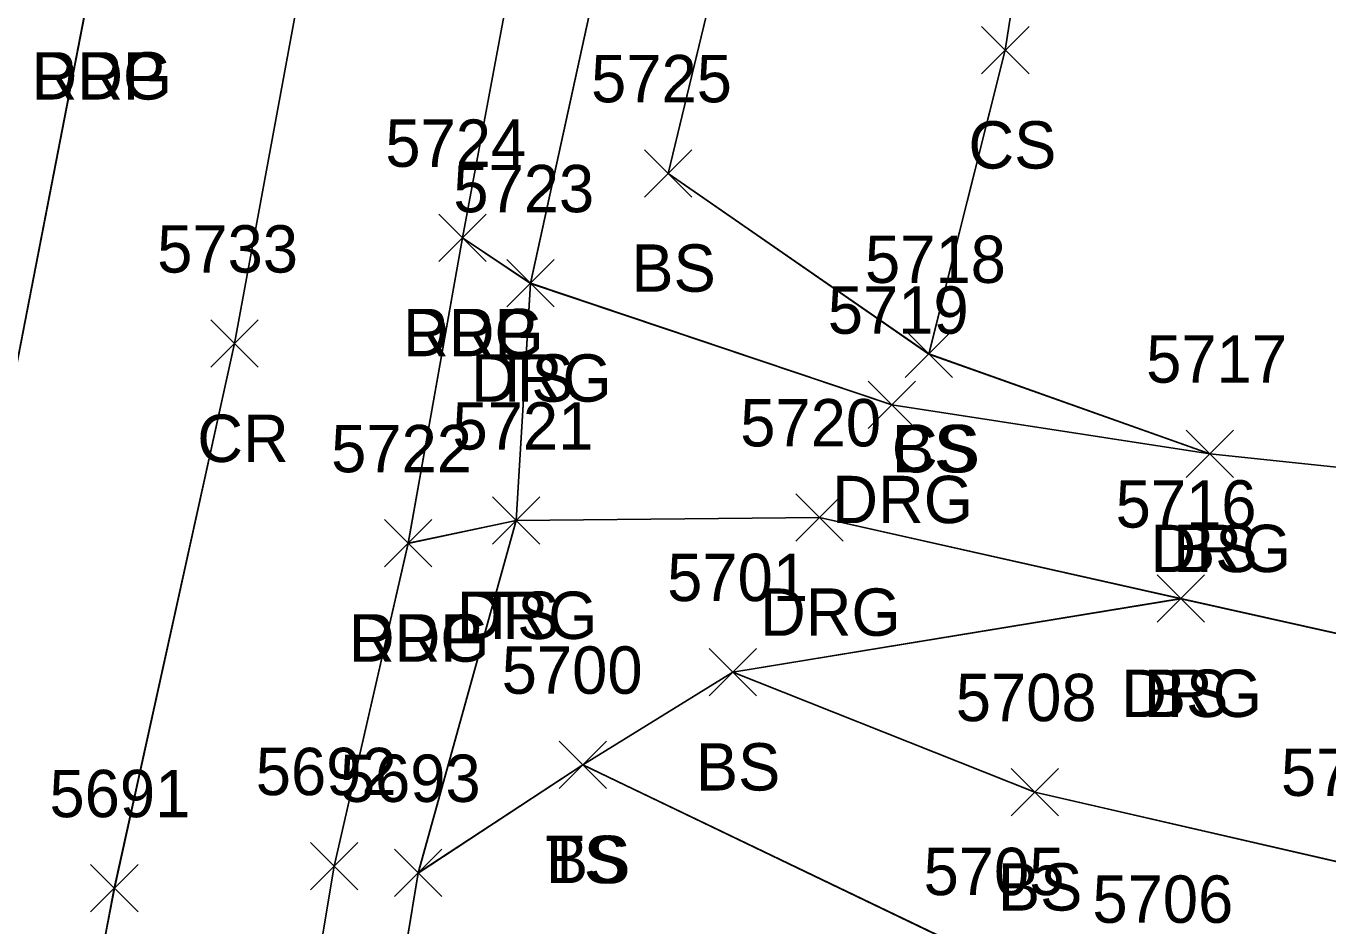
# Model space of a CAD drawing. Extents: x 1554668 to 1563881, y 831386 to 834374.
# Drawn here: x 1561791.4 to 1561846.4, y 833346.9 to 833385 of the extents above; entities that cross this region are included whole.
import ezdxf

# ---------------------------------------------------------------- set-up
doc = ezdxf.new("R2010")
doc.units = 0
for name, color, linetype in [('L_A', 7, 'Continuous'), ('L_I', 7, 'Continuous'), ('L_TIC', 7, 'Continuous'), ('LELB', 7, 'Continuous'), ('P_A', 7, 'Continuous'), ('P_I', 7, 'Continuous'), ('P_TIC', 7, 'Continuous'), ('PET', 7, 'Continuous'), ('PRC', 7, 'Continuous'), ('R_A', 7, 'Continuous'), ('R_I', 7, 'Continuous'), ('R_TIC', 7, 'Continuous'), ('RDG', 7, 'Continuous')]:
    doc.layers.add(name, color=color, linetype=linetype)

msp = doc.modelspace()

# ---------------------------------------------------------------- linework, layer by layer
at = {"layer": 'L_TIC'}
for points in [[(1561831.772, 833382.931), (1561833.772, 833384.931)], [(1561833.772, 833382.931), (1561831.772, 833384.931)], [(1561817.534, 833377.73), (1561819.534, 833379.73)], [(1561819.534, 833377.73), (1561817.534, 833379.73)], [(1561811.717, 833373.086), (1561813.717, 833375.086)], [(1561813.717, 833373.086), (1561811.717, 833375.086)], [(1561828.538, 833370.101), (1561830.538, 833372.101)], [(1561830.538, 833370.101), (1561828.538, 833372.101)], [(1561828.538, 833370.101), (1561830.538, 833372.101)], [(1561830.538, 833370.101), (1561828.538, 833372.101)], [(1561840.414, 833365.888), (1561842.414, 833367.888)], [(1561842.414, 833365.888), (1561840.414, 833367.888)], [(1561811.115, 833363.064), (1561813.115, 833365.064)], [(1561813.115, 833363.064), (1561811.115, 833365.064)], [(1561839.178, 833359.768), (1561841.178, 833361.768)], [(1561841.178, 833359.768), (1561839.178, 833361.768)], [(1561820.259, 833356.663), (1561822.259, 833358.663)], [(1561822.259, 833356.663), (1561820.259, 833358.663)], [(1561820.259, 833356.663), (1561822.259, 833358.663)], [(1561822.259, 833356.663), (1561820.259, 833358.663)], [(1561813.926, 833352.75), (1561815.926, 833354.75)], [(1561815.926, 833352.75), (1561813.926, 833354.75)], [(1561813.926, 833352.75), (1561815.926, 833354.75)], [(1561815.926, 833352.75), (1561813.926, 833354.75)], [(1561833.017, 833351.592), (1561835.017, 833353.592)], [(1561835.017, 833351.592), (1561833.017, 833353.592)], [(1561806.971, 833348.18), (1561808.971, 833350.18)], [(1561808.971, 833348.18), (1561806.971, 833350.18)], [(1561806.971, 833348.18), (1561808.971, 833350.18)], [(1561808.971, 833348.18), (1561806.971, 833350.18)]]:
    msp.add_lwpolyline(points, dxfattribs=at)
at = {"layer": 'LELB'}
for points in [[(1561841.414, 833366.888), (1561829.538, 833371.101), (1561818.534, 833378.73), (1561823.688, 833400.076), (1561828.271, 833434.265), (1561833.191, 833445.334), (1561836.067, 833469.47), (1561840.466, 833492.775), (1561845.508, 833506.736), (1561853.324, 833557.227)], [(1561841.414, 833366.885), (1561829.538, 833371.095), (1561818.535, 833378.726), (1561823.688, 833400.072), (1561828.271, 833434.262), (1561833.192, 833445.33), (1561836.066, 833469.461), (1561840.465, 833492.765), (1561845.509, 833506.732), (1561853.326, 833557.225)], [(1561841.414, 833366.885), (1561829.538, 833371.095), (1561818.535, 833378.726), (1561823.688, 833400.072), (1561828.271, 833434.262), (1561833.192, 833445.33), (1561836.066, 833469.461), (1561840.465, 833492.765), (1561845.509, 833506.732), (1561853.326, 833557.225)], [(1561841.414, 833366.885), (1561829.538, 833371.095), (1561818.535, 833378.726), (1561823.688, 833400.072), (1561828.271, 833434.262), (1561833.192, 833445.33), (1561836.066, 833469.461), (1561840.465, 833492.765), (1561845.509, 833506.732), (1561853.326, 833557.225)], [(1561829.538, 833371.101), (1561832.772, 833383.931), (1561835.237, 833399.815), (1561850.214, 833430.878)], [(1561829.538, 833371.095), (1561832.772, 833383.929), (1561835.236, 833399.812), (1561850.216, 833430.872)], [(1561829.538, 833371.095), (1561832.772, 833383.929), (1561835.236, 833399.812), (1561850.216, 833430.872)], [(1561829.538, 833371.095), (1561832.772, 833383.929), (1561835.236, 833399.812), (1561850.216, 833430.872)], [(1561802.802, 833317.896), (1561807.971, 833349.18), (1561812.115, 833364.064), (1561812.717, 833374.086), (1561818.657, 833401.257)], [(1561802.805, 833317.894), (1561807.975, 833349.179), (1561812.115, 833364.063), (1561812.716, 833374.079), (1561818.656, 833401.248)], [(1561802.805, 833317.894), (1561807.975, 833349.179), (1561812.115, 833364.063), (1561812.716, 833374.079), (1561818.656, 833401.248)], [(1561802.805, 833317.894), (1561807.975, 833349.179), (1561812.115, 833364.063), (1561812.716, 833374.079), (1561818.656, 833401.248)], [(1561807.971, 833349.18), (1561814.926, 833353.75), (1561821.259, 833357.663), (1561840.178, 833360.768)], [(1561807.975, 833349.179), (1561814.926, 833353.748), (1561821.259, 833357.662), (1561840.179, 833360.759)], [(1561807.975, 833349.179), (1561814.926, 833353.748), (1561821.259, 833357.662), (1561840.179, 833360.759)], [(1561807.975, 833349.179), (1561814.926, 833353.748), (1561821.259, 833357.662), (1561840.179, 833360.759)], [(1561821.259, 833357.663), (1561834.017, 833352.592), (1561847.759, 833349.436), (1561844.879, 833338.765)], [(1561821.259, 833357.662), (1561834.017, 833352.592), (1561847.76, 833349.427), (1561844.878, 833338.763)], [(1561821.259, 833357.662), (1561834.017, 833352.592), (1561847.76, 833349.427), (1561844.878, 833338.763)], [(1561821.259, 833357.662), (1561834.017, 833352.592), (1561847.76, 833349.427), (1561844.878, 833338.763)], [(1561814.926, 833353.75), (1561832.657, 833345.244), (1561839.843, 833344.075), (1561839.671, 833339.692)], [(1561814.926, 833353.748), (1561832.658, 833345.234), (1561839.843, 833344.071), (1561839.671, 833339.686)], [(1561814.926, 833353.748), (1561832.658, 833345.234), (1561839.843, 833344.071), (1561839.671, 833339.686)], [(1561814.926, 833353.748), (1561832.658, 833345.234), (1561839.843, 833344.071), (1561839.671, 833339.686)]]:
    msp.add_lwpolyline(points, dxfattribs=at)
at = {"layer": 'P_TIC'}
for points in [[(1561808.846, 833375.005), (1561810.846, 833377.005)], [(1561810.846, 833375.005), (1561808.846, 833377.005)], [(1561799.21, 833370.538), (1561801.21, 833372.538)], [(1561801.21, 833370.538), (1561799.21, 833372.538)], [(1561806.557, 833362.104), (1561808.557, 833364.104)], [(1561808.557, 833362.104), (1561806.557, 833364.104)], [(1561803.42, 833348.467), (1561805.42, 833350.467)], [(1561805.42, 833348.467), (1561803.42, 833350.467)], [(1561794.14, 833347.536), (1561796.14, 833349.536)], [(1561796.14, 833347.536), (1561794.14, 833349.536)]]:
    msp.add_lwpolyline(points, dxfattribs=at)
at = {"layer": 'PET'}
for points in [[(1561772.446, 833192.579), (1561778.438, 833223.18), (1561783.455, 833245.681), (1561787.292, 833266.873), (1561787.951, 833268.214), (1561791.576, 833284.83), (1561800.188, 833324.049), (1561804.421, 833349.461), (1561807.556, 833363.095), (1561809.846, 833376.001), (1561814.768, 833402.403)], [(1561772.446, 833192.579), (1561778.438, 833223.18), (1561783.455, 833245.681), (1561787.292, 833266.873), (1561787.951, 833268.214), (1561791.576, 833284.83), (1561800.188, 833324.049), (1561804.421, 833349.461), (1561807.556, 833363.095), (1561809.846, 833376.001), (1561814.768, 833402.403)], [(1561772.446, 833192.579), (1561778.438, 833223.18), (1561783.455, 833245.681), (1561787.292, 833266.873), (1561787.951, 833268.214), (1561791.576, 833284.83), (1561800.188, 833324.049), (1561804.421, 833349.461), (1561807.556, 833363.095), (1561809.846, 833376.001), (1561814.768, 833402.403)], [(1561772.448, 833192.582), (1561778.438, 833223.182), (1561783.456, 833245.678), (1561787.29, 833266.873), (1561787.952, 833268.21), (1561791.573, 833284.832), (1561800.187, 833324.054), (1561804.42, 833349.467), (1561807.557, 833363.104), (1561809.846, 833376.005), (1561814.767, 833402.407)], [(1561794.153, 833386.847), (1561787.73, 833353.765), (1561780.101, 833323.092), (1561773.948, 833293.345), (1561769.473, 833270.793), (1561767.205, 833260.262), (1561761.663, 833232.621), (1561756.047, 833208.855), (1561751.508, 833175.557)], [(1561794.155, 833386.844), (1561787.73, 833353.76), (1561780.101, 833323.09), (1561773.949, 833293.347), (1561769.473, 833270.791), (1561767.205, 833260.264), (1561761.664, 833232.622), (1561756.046, 833208.853), (1561751.508, 833175.556)], [(1561794.155, 833386.844), (1561787.73, 833353.76), (1561780.101, 833323.09), (1561773.949, 833293.347), (1561769.473, 833270.791), (1561767.205, 833260.264), (1561761.664, 833232.622), (1561756.046, 833208.853), (1561751.508, 833175.556)], [(1561794.155, 833386.844), (1561787.73, 833353.76), (1561780.101, 833323.09), (1561773.949, 833293.347), (1561769.473, 833270.791), (1561767.205, 833260.264), (1561761.664, 833232.622), (1561756.046, 833208.853), (1561751.508, 833175.556)]]:
    msp.add_lwpolyline(points, dxfattribs=at)
at = {"layer": 'PRC'}
for points in [[(1562300.293, 833002.635), (1562265.056, 833007.76), (1562229.752, 833015.899), (1562188.56, 833027.158), (1562163.867, 833032.834), (1562128.368, 833039.745), (1562080.008, 833048.853), (1562037.166, 833057.37), (1561989.079, 833066.767), (1561944.749, 833075.337), (1561893.656, 833085.488), (1561855.803, 833092.68), (1561805.738, 833106.779), (1561782.445, 833121.396), (1561772.46, 833130.936), (1561764.816, 833144.509), (1561760.941, 833173.068), (1561763.812, 833193.359), (1561770.109, 833225.658), (1561775.835, 833254.581), (1561787.627, 833309.043), (1561795.14, 833348.536), (1561800.21, 833371.538), (1561806.437, 833405.192)], [(1562300.297, 833002.634), (1562265.06, 833007.759), (1562229.751, 833015.899), (1562188.563, 833027.157), (1562163.87, 833032.838), (1562128.369, 833039.745), (1562080.013, 833048.851), (1562037.119, 833057.379), (1561989.031, 833066.776), (1561944.699, 833075.346), (1561893.607, 833085.494), (1561855.757, 833092.686), (1561805.685, 833106.789), (1561782.448, 833121.397), (1561772.461, 833130.936), (1561764.814, 833144.506), (1561760.941, 833173.07), (1561763.813, 833193.362), (1561770.108, 833225.654), (1561775.838, 833254.58), (1561787.632, 833309.041), (1561795.141, 833348.53), (1561800.212, 833371.537), (1561806.439, 833405.19)], [(1562300.297, 833002.634), (1562265.06, 833007.759), (1562229.751, 833015.899), (1562188.563, 833027.157), (1562163.87, 833032.838), (1562128.369, 833039.745), (1562080.013, 833048.851), (1562037.119, 833057.379), (1561989.031, 833066.776), (1561944.699, 833075.346), (1561893.607, 833085.494), (1561855.757, 833092.686), (1561805.685, 833106.789), (1561782.448, 833121.397), (1561772.461, 833130.936), (1561764.814, 833144.506), (1561760.941, 833173.07), (1561763.813, 833193.362), (1561770.108, 833225.654), (1561775.838, 833254.58), (1561787.632, 833309.041), (1561795.141, 833348.53), (1561800.212, 833371.537), (1561806.439, 833405.19)], [(1562300.297, 833002.634), (1562265.06, 833007.759), (1562229.751, 833015.899), (1562188.563, 833027.157), (1562163.87, 833032.838), (1562128.369, 833039.745), (1562080.013, 833048.851), (1562037.119, 833057.379), (1561989.031, 833066.776), (1561944.699, 833075.346), (1561893.607, 833085.494), (1561855.757, 833092.686), (1561805.685, 833106.789), (1561782.448, 833121.397), (1561772.461, 833130.936), (1561764.814, 833144.506), (1561760.941, 833173.07), (1561763.813, 833193.362), (1561770.108, 833225.654), (1561775.838, 833254.58), (1561787.632, 833309.041), (1561795.141, 833348.53), (1561800.212, 833371.537), (1561806.439, 833405.19)]]:
    msp.add_lwpolyline(points, dxfattribs=at)
at = {"layer": 'R_TIC'}
for points in [[(1561808.846, 833375.005), (1561810.846, 833377.005)], [(1561810.846, 833375.005), (1561808.846, 833377.005)], [(1561811.717, 833373.086), (1561813.717, 833375.086)], [(1561813.717, 833373.086), (1561811.717, 833375.086)], [(1561826.974, 833367.955), (1561828.974, 833369.955)], [(1561828.974, 833367.955), (1561826.974, 833369.955)], [(1561840.414, 833365.888), (1561842.414, 833367.888)], [(1561842.414, 833365.888), (1561840.414, 833367.888)], [(1561811.115, 833363.064), (1561813.115, 833365.064)], [(1561813.115, 833363.064), (1561811.115, 833365.064)], [(1561823.922, 833363.197), (1561825.922, 833365.197)], [(1561825.922, 833363.197), (1561823.922, 833365.197)], [(1561806.557, 833362.104), (1561808.557, 833364.104)], [(1561808.557, 833362.104), (1561806.557, 833364.104)], [(1561839.178, 833359.768), (1561841.178, 833361.768)], [(1561841.178, 833359.768), (1561839.178, 833361.768)]]:
    msp.add_lwpolyline(points, dxfattribs=at)
at = {"layer": 'RDG'}
for points in [[(1561864.445, 833364.463), (1561841.414, 833366.888), (1561827.974, 833368.955), (1561812.717, 833374.086), (1561809.846, 833376.005)], [(1561864.446, 833364.456), (1561841.414, 833366.885), (1561827.974, 833368.949), (1561812.716, 833374.079), (1561809.846, 833376.001)], [(1561864.446, 833364.456), (1561841.414, 833366.885), (1561827.974, 833368.949), (1561812.716, 833374.079), (1561809.846, 833376.001)], [(1561864.446, 833364.456), (1561841.414, 833366.885), (1561827.974, 833368.949), (1561812.716, 833374.079), (1561809.846, 833376.001)], [(1561863.09, 833355.654), (1561840.179, 833360.759), (1561824.922, 833364.196), (1561812.115, 833364.063), (1561807.556, 833363.095)], [(1561863.09, 833355.654), (1561840.179, 833360.759), (1561824.922, 833364.196), (1561812.115, 833364.063), (1561807.556, 833363.095)], [(1561863.09, 833355.654), (1561840.179, 833360.759), (1561824.922, 833364.196), (1561812.115, 833364.063), (1561807.556, 833363.095)], [(1561863.09, 833355.659), (1561840.178, 833360.768), (1561824.922, 833364.197), (1561812.115, 833364.064), (1561807.557, 833363.104)]]:
    msp.add_lwpolyline(points, dxfattribs=at)

# ---------------------------------------------------------------- texts
at = {"layer": 'L_A'}
for s, p in [('CS', (1561831.213, 833378.931)), ('BS', (1561816.975, 833373.73)), ('TS', (1561811.126, 833369.086)), ('CS', (1561827.979, 833366.101)), ('BS', (1561827.979, 833366.101)), ('BS', (1561839.855, 833361.888)), ('TS', (1561810.524, 833359.064)), ('BS', (1561838.619, 833355.768)), ('BS', (1561819.7, 833352.663)), ('BS', (1561819.7, 833352.663)), ('TS', (1561813.335, 833348.75)), ('BS', (1561813.367, 833348.75)), ('BS', (1561832.458, 833347.592))]:
    msp.add_text(s, height=2, dxfattribs=at).set_placement(p)
at = {"layer": 'L_I'}
for s, p in [('5725', (1561815.275, 833381.73)), ('5723', (1561809.457, 833377.086)), ('5718', (1561826.845, 833374.101)), ('5718', (1561826.845, 833374.101)), ('5717', (1561838.721, 833369.888)), ('5721', (1561809.422, 833367.064)), ('5716', (1561837.43, 833363.768)), ('5701', (1561818.488, 833360.663)), ('5701', (1561818.488, 833360.663)), ('5700', (1561811.501, 833356.75)), ('5700', (1561811.501, 833356.75)), ('5708', (1561830.679, 833355.592)), ('5709', (1561844.412, 833352.436)), ('5693', (1561804.663, 833352.18)), ('5693', (1561804.663, 833352.18)), ('5705', (1561829.319, 833348.244)), ('5706', (1561836.449, 833347.075))]:
    msp.add_text(s, height=2, dxfattribs=at).set_placement(p)
at = {"layer": 'P_A'}
for s, p in [('RDP', (1561791.642, 833381.847)), ('RDP', (1561807.334, 833371.005)), ('CR', (1561798.643, 833366.538)), ('RDP', (1561805.045, 833358.104))]:
    msp.add_text(s, height=2, dxfattribs=at).set_placement(p)
at = {"layer": 'P_I'}
for s, p in [('5724', (1561806.586, 833379.005)), ('5733', (1561796.95, 833374.538)), ('5722', (1561804.297, 833366.104)), ('5692', (1561801.113, 833352.467)), ('5691', (1561792.399, 833351.536))]:
    msp.add_text(s, height=2, dxfattribs=at).set_placement(p)
at = {"layer": 'R_A'}
for p in [(1561791.642, 833381.847), (1561807.334, 833371.005), (1561810.205, 833369.086), (1561825.463, 833363.955), (1561838.902, 833361.888), (1561809.603, 833359.064), (1561822.41, 833359.197), (1561805.045, 833358.104), (1561837.666, 833355.768)]:
    msp.add_text('DRG', height=2, dxfattribs=at).set_placement(p)
at = {"layer": 'R_I'}
for s, p in [('5724', (1561806.586, 833379.005)), ('5723', (1561809.457, 833377.086)), ('5719', (1561825.274, 833371.955)), ('5717', (1561838.721, 833369.888)), ('5721', (1561809.422, 833367.064)), ('5720', (1561821.575, 833367.197)), ('5722', (1561804.297, 833366.104)), ('5716', (1561837.43, 833363.768))]:
    msp.add_text(s, height=2, dxfattribs=at).set_placement(p)

doc.saveas('drawing.dxf')
